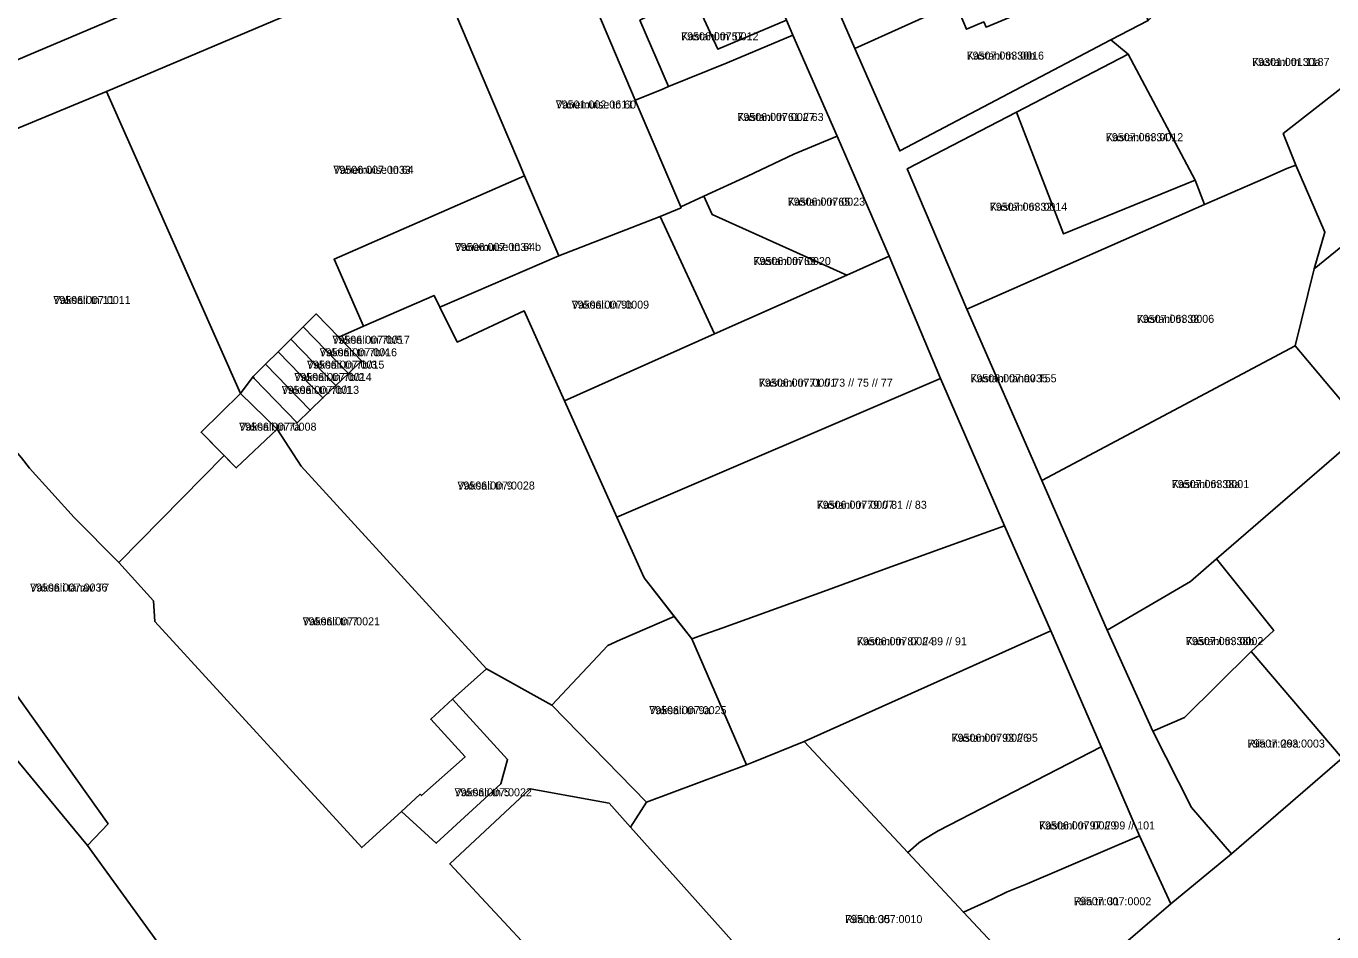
# Model space of a CAD drawing. Extents: x 643847 to 663718, y 6468443 to 6482775.
# Drawn here: x 658589.8 to 658834.6, y 6473255.6 to 6473425.5 of the extents above; entities that cross this region are included whole.
import ezdxf

# ---------------------------------------------------------------- set-up
doc = ezdxf.new("R2010")
doc.units = 0
for name, color, linetype in [('L_AADRESS', 7, 'Continuous'), ('PIIR', 7, 'Continuous'), ('TUNNUS', 7, 'Continuous')]:
    doc.layers.add(name, color=color, linetype=linetype)

msp = doc.modelspace()

# ---------------------------------------------------------------- linework, layer by layer
at = {"layer": 'PIIR'}
for points in [[(658352.42, 6473525.64), (658391.88, 6473482.08), (658396.74, 6473486.49), (658406.86, 6473476.1), (658413.24, 6473482), (658427.32, 6473466.48), (658432.48, 6473460.76), (658483.05, 6473404.88), (658577.8, 6473300.21), (658601.3, 6473271.83), (658617.93, 6473248.91), (658693.58, 6473165.93), (658667.09, 6473142.75), (658660.36, 6473146.34), (658618.09, 6473105.54), (658510.07, 6473222.36), (658505.7, 6473227.37), (658508.51, 6473230.27), (658490.61, 6473249.76), (658445.73, 6473274.17), (658391.3, 6473304.26), (658372.55, 6473316.25), (658325.22, 6473349.95)], [(658583.03, 6473417.07), (658626.66, 6473435.57), (658628.88, 6473436.51), (658649.93, 6473445.42), (658671, 6473454.4), (658691.92, 6473463.18), (658712.63, 6473472.01), (658724.84, 6473477.65), (658800.4, 6473509.39), (658804.98, 6473498.15), (658785.73, 6473489.74), (658737.94, 6473469.31), (658726.45, 6473464.29), (658718.34, 6473460.71), (658716.6, 6473461.47), (658716.02, 6473460.12), (658703.71, 6473454.91), (658702, 6473454.21), (658684.52, 6473446.9), (658665.58, 6473438.99), (658604.84, 6473413.21), (658567.57, 6473397.77)], [(658584.09, 6473493.04), (658592.12, 6473481.4), (658605.87, 6473488.59), (658612.19, 6473474.52), (658610.02, 6473473.51), (658626.66, 6473435.57), (658583.03, 6473417.07)], [(658738.91, 6473435.71), (658745.17, 6473421.3), (658753.55, 6473402.1), (658793.15, 6473422.92), (658796.36, 6473420.25), (658775.44, 6473409.35), (658754.98, 6473398.76), (658766.13, 6473372.39), (658780.18, 6473340.27), (658792.45, 6473312.19), (658800.98, 6473293.24), (658808.26, 6473278.98), (658815.73, 6473270.26), (658804.39, 6473260.9), (658798.53, 6473273.64), (658791.3, 6473290.35), (658781.9, 6473312.07), (658773.23, 6473331.78), (658761.22, 6473359.39), (658751.59, 6473382.33), (658741.84, 6473404.85), (658733.55, 6473423.79), (658732.32, 6473426.61)], [(658861.3, 6473404.41), (658831.27, 6473379.95), (658833.27, 6473386.84), (658827.82, 6473399.42), (658825.41, 6473405.35), (658846.27, 6473421.59)], [(658588.95, 6473344.51), (658590.42, 6473342.6), (658598.83, 6473333.37), (658607.16, 6473324.91), (658613.65, 6473317.73), (658613.9, 6473313.86), (658652.71, 6473271.43), (658660.14, 6473278.22), (658666.67, 6473272.25), (658678.8, 6473283.4), (658680.06, 6473287.95), (658669.74, 6473299.24), (658676.1, 6473304.96), (658688.34, 6473298.13), (658706.07, 6473279.98), (658703.1, 6473275.28), (658699.1, 6473279.76), (658684.26, 6473282.46), (658669.2, 6473268.37), (658718.1, 6473215.89)], [(658617.93, 6473248.91), (658601.3, 6473271.83), (658605.17, 6473275.88), (658568.09, 6473328.03)], [(658874.2, 6473286.88), (658829.76, 6473248.96), (658813.46, 6473235.12), (658760.72, 6473188.59), (658745.48, 6473177.42), (658741.68, 6473174.16), (658711.01, 6473147.88), (658693.58, 6473165.93), (658722.67, 6473191.45), (658735.36, 6473202.16), (658760.31, 6473223.21), (658781.85, 6473241.8), (658788.91, 6473247.59), (658804.39, 6473260.9), (658815.73, 6473270.26), (658836.52, 6473288.19)]]:
    msp.add_lwpolyline(points, dxfattribs=at)
for points in [[(658738.91, 6473435.71), (658761.36, 6473444.84), (658790.06, 6473456.51), (658797.34, 6473436.79), (658796.17, 6473436.34), (658769.74, 6473425.31), (658769.32, 6473426.29), (658766.08, 6473424.9), (658763.99, 6473429.83), (658745.17, 6473421.3)], [(658678.49, 6473408.6), (658665.58, 6473438.99), (658684.52, 6473446.9), (658688.6, 6473437.49), (658692.11, 6473429.63), (658695.69, 6473431.14), (658703.99, 6473411.63), (658712.5, 6473391.63), (658712.58, 6473391.44), (658708.65, 6473389.77), (658689.63, 6473382.39), (658683.25, 6473397.43), (658682.12, 6473400.09)], [(658732.32, 6473426.61), (658719.44, 6473421.18), (658714.73, 6473431.54), (658704.87, 6473426.6), (658710.23, 6473414.15), (658708.84, 6473413.58), (658703.99, 6473411.63), (658695.69, 6473431.14), (658709.42, 6473437.14), (658717.31, 6473440.56), (658724.8, 6473443.88)], [(658793.15, 6473422.92), (658800.14, 6473426.58), (658801.06, 6473427.49), (658829.43, 6473443.27), (658829.58, 6473443.61), (658829.98, 6473443.98), (658833.47, 6473439.91), (658832.15, 6473438.79), (658837.94, 6473432.06), (658839.37, 6473433.2), (658848.13, 6473422.91), (658846.57, 6473421.5), (658846.27, 6473421.59), (658825.41, 6473405.35), (658827.82, 6473399.42), (658826.14, 6473398.77), (658822.08, 6473396.98), (658810.71, 6473392.07), (658808.96, 6473396.59), (658796.36, 6473420.25)], [(658665.58, 6473438.99), (658678.49, 6473408.6), (658682.12, 6473400.09), (658683.25, 6473397.43), (658647.53, 6473381.78), (658653.02, 6473369.24), (658648.44, 6473367.16), (658644.19, 6473371.51), (658641.76, 6473369.09), (658639.44, 6473366.8), (658637.05, 6473364.44), (658634.7, 6473362.12), (658632.35, 6473359.79), (658630, 6473356.62), (658604.84, 6473413.21)], [(658753.55, 6473402.1), (658745.17, 6473421.3), (658763.99, 6473429.83), (658766.08, 6473424.9), (658769.32, 6473426.29), (658769.74, 6473425.31), (658796.17, 6473436.34), (658800.14, 6473426.58), (658793.15, 6473422.92)], [(658733.55, 6473423.79), (658721.2, 6473418.59), (658710.23, 6473414.15), (658704.87, 6473426.6), (658714.73, 6473431.54), (658719.44, 6473421.18), (658732.32, 6473426.61)], [(658741.84, 6473404.85), (658733.68, 6473401.49), (658725.03, 6473397.33), (658716.83, 6473393.61), (658712.5, 6473391.63), (658703.99, 6473411.63), (658708.84, 6473413.58), (658710.23, 6473414.15), (658721.2, 6473418.59), (658733.55, 6473423.79)], [(658775.44, 6473409.35), (658796.36, 6473420.25), (658808.96, 6473396.59), (658784.26, 6473386.53)], [(658496.72, 6473417.32), (658568.09, 6473328.03), (658605.17, 6473275.88), (658601.3, 6473271.83), (658577.8, 6473300.21), (658483.05, 6473404.88), (658493.36, 6473414.41)], [(658630, 6473356.62), (658622.6, 6473349.34), (658626.92, 6473344.94), (658607.16, 6473324.91), (658598.83, 6473333.37), (658590.42, 6473342.6), (658588.95, 6473344.51), (658575.52, 6473360.24), (658574.14, 6473361.52), (658559.79, 6473377.4), (658572.54, 6473382.28), (658572.66, 6473386.18), (658569.3, 6473394.9), (658567.57, 6473397.77), (658604.84, 6473413.21)], [(658754.98, 6473398.76), (658775.44, 6473409.35), (658784.26, 6473386.53), (658808.96, 6473396.59), (658810.71, 6473392.07), (658766.13, 6473372.39)], [(658751.59, 6473382.33), (658743.63, 6473378.79), (658718.4, 6473390.16), (658716.83, 6473393.61), (658725.03, 6473397.33), (658733.68, 6473401.49), (658741.84, 6473404.85)], [(658869.51, 6473315.83), (658840.95, 6473349.76), (658827.68, 6473365.53), (658831.27, 6473379.95), (658861.3, 6473404.41), (658909.1, 6473348.62)], [(658766.13, 6473372.39), (658810.71, 6473392.07), (658822.08, 6473396.98), (658826.14, 6473398.77), (658827.82, 6473399.42), (658833.27, 6473386.84), (658831.27, 6473379.95), (658827.68, 6473365.53), (658780.18, 6473340.27)], [(658683.25, 6473397.43), (658689.63, 6473382.39), (658667.36, 6473372.77), (658666.26, 6473374.99), (658653.02, 6473369.24), (658647.53, 6473381.78)], [(658718.85, 6473367.76), (658708.65, 6473389.77), (658712.58, 6473391.44), (658712.5, 6473391.63), (658716.83, 6473393.61), (658718.4, 6473390.16), (658743.63, 6473378.79)], [(658718.85, 6473367.76), (658690.72, 6473355.25), (658683.14, 6473372.11), (658670.62, 6473366.24), (658667.36, 6473372.77), (658689.63, 6473382.39), (658708.65, 6473389.77)], [(658761.22, 6473359.39), (658700.53, 6473333.43), (658690.72, 6473355.25), (658718.85, 6473367.76), (658743.63, 6473378.79), (658751.59, 6473382.33)], [(658688.34, 6473298.13), (658676.1, 6473304.96), (658641.38, 6473342.97), (658636.85, 6473349.89), (658630, 6473356.62), (658632.35, 6473359.79), (658632.53, 6473359.42), (658640.59, 6473351.07), (658643.07, 6473353.46), (658645.44, 6473355.76), (658647.86, 6473358.09), (658650.2, 6473360.36), (658652.67, 6473362.75), (658648.44, 6473367.16), (658653.02, 6473369.24), (658666.26, 6473374.99), (658667.36, 6473372.77), (658670.62, 6473366.24), (658683.14, 6473372.11), (658690.72, 6473355.25), (658700.53, 6473333.43), (658705.65, 6473322.03), (658711.3, 6473314.8), (658701.16, 6473310.38), (658698.87, 6473309.34)], [(658641.76, 6473369.09), (658644.19, 6473371.51), (658648.44, 6473367.16), (658652.67, 6473362.75), (658650.2, 6473360.36)], [(658639.44, 6473366.8), (658641.76, 6473369.09), (658650.2, 6473360.36), (658647.86, 6473358.09)], [(658637.05, 6473364.44), (658639.44, 6473366.8), (658647.86, 6473358.09), (658645.44, 6473355.76)], [(658780.18, 6473340.27), (658827.68, 6473365.53), (658840.95, 6473349.76), (658812.96, 6473325.59), (658808.04, 6473321.35), (658792.45, 6473312.19)], [(658634.7, 6473362.12), (658637.05, 6473364.44), (658645.44, 6473355.76), (658643.07, 6473353.46)], [(658632.53, 6473359.42), (658632.35, 6473359.79), (658634.7, 6473362.12), (658643.07, 6473353.46), (658640.59, 6473351.07)], [(658773.23, 6473331.78), (658750.52, 6473323.56), (658739.27, 6473319.49), (658720.42, 6473312.67), (658716.81, 6473311.37), (658714.6, 6473310.57), (658705.65, 6473322.03), (658700.53, 6473333.43), (658761.22, 6473359.39)], [(658622.6, 6473349.34), (658630, 6473356.62), (658636.85, 6473349.89), (658629.18, 6473342.63)], [(658613.9, 6473313.86), (658613.65, 6473317.73), (658607.16, 6473324.91), (658626.92, 6473344.94), (658629.18, 6473342.63), (658636.85, 6473349.89), (658641.38, 6473342.97), (658676.1, 6473304.96), (658669.74, 6473299.24), (658665.64, 6473295.49), (658672.07, 6473288.47), (658663.9, 6473281.18), (658663.66, 6473281.45), (658660.14, 6473278.22), (658652.71, 6473271.43)], [(658836.52, 6473288.19), (658819.41, 6473308.19), (658823.67, 6473312.18), (658812.96, 6473325.59), (658840.95, 6473349.76), (658869.51, 6473315.83)], [(658773.23, 6473331.78), (658781.9, 6473312.07), (658735.62, 6473291.33), (658726.08, 6473287.44), (658724.83, 6473286.98), (658714.6, 6473310.57), (658716.81, 6473311.37), (658720.42, 6473312.67), (658739.27, 6473319.49), (658750.52, 6473323.56)], [(658792.45, 6473312.19), (658808.04, 6473321.35), (658812.96, 6473325.59), (658823.67, 6473312.18), (658819.41, 6473308.19), (658806.95, 6473295.85), (658800.98, 6473293.24)], [(658688.34, 6473298.13), (658698.87, 6473309.34), (658701.16, 6473310.38), (658711.3, 6473314.8), (658714.6, 6473310.57), (658724.83, 6473286.98), (658706.07, 6473279.98)], [(658781.9, 6473312.07), (658791.3, 6473290.35), (658760.79, 6473274.56), (658757.74, 6473272.75), (658757.12, 6473272.3), (658755.07, 6473270.49), (658735.62, 6473291.33)], [(658815.73, 6473270.26), (658808.26, 6473278.98), (658800.98, 6473293.24), (658806.95, 6473295.85), (658819.41, 6473308.19), (658836.52, 6473288.19)], [(658660.14, 6473278.22), (658663.66, 6473281.45), (658663.9, 6473281.18), (658672.07, 6473288.47), (658665.64, 6473295.49), (658669.74, 6473299.24), (658680.06, 6473287.95), (658678.8, 6473283.4), (658666.67, 6473272.25)], [(658735.62, 6473291.33), (658755.07, 6473270.49), (658765.5, 6473259.32), (658776.42, 6473247.62), (658781.85, 6473241.8), (658760.31, 6473223.21), (658740.7, 6473245.26), (658734.73, 6473239.88), (658703.1, 6473275.28), (658706.07, 6473279.98), (658724.83, 6473286.98), (658726.08, 6473287.44)], [(658791.3, 6473290.35), (658798.53, 6473273.64), (658777.43, 6473264.66), (658773.69, 6473263.13), (658770.89, 6473261.76), (658765.5, 6473259.32), (658755.07, 6473270.49), (658757.12, 6473272.3), (658757.74, 6473272.75), (658760.79, 6473274.56)], [(658669.2, 6473268.37), (658684.26, 6473282.46), (658699.1, 6473279.76), (658703.1, 6473275.28), (658734.73, 6473239.88), (658739.22, 6473234.86), (658718.1, 6473215.89)], [(658804.39, 6473260.9), (658788.91, 6473247.59), (658783.63, 6473253.54), (658776.42, 6473247.62), (658765.5, 6473259.32), (658770.89, 6473261.76), (658773.69, 6473263.13), (658777.43, 6473264.66), (658798.53, 6473273.64)]]:
    msp.add_lwpolyline(points, close=True, dxfattribs=at)

# ---------------------------------------------------------------- texts
at = {"layer": 'L_AADRESS'}
for s, p in [('Kastani tn 57', (658712.58, 6473422.84)), ('Kastani tn 30b', (658766.1, 6473419.22)), ('Kastani tn 30a', (658819.62, 6473418.03)), ('Vanemuise tn 60', (658689.08, 6473410.05)), ('Kastani tn 61 // 63', (658723.12, 6473407.71)), ('Kastani tn 34', (658792.2, 6473403.92)), ('Vanemuise tn 64', (658647.39, 6473397.8)), ('Kastani tn 65', (658732.56, 6473391.82)), ('Kastani tn 32', (658770.45, 6473390.87)), ('Vanemuise tn 64b', (658670.15, 6473383.33)), ('Kastani tn 69', (658726.14, 6473380.69)), ('Vaksali tn 11', (658594.89, 6473373.39)), ('Vaksali tn 9b', (658692.07, 6473372.51)), ('Kastani tn 38', (658798, 6473369.85)), ('Vaksali tn 7b/5', (658647.21, 6473365.93)), ('Vaksali tn 7b/4', (658644.82, 6473363.58)), ('Vaksali tn 7b/3', (658642.45, 6473361.26)), ('Vaksali tn 7b/2', (658640.07, 6473358.94)), ('Kastani tänav T55', (658766.8, 6473358.7)), ('Vaksali tn 7b/1', (658637.71, 6473356.53)), ('Kastani tn 71 // 73 // 75 // 77', (658727.16, 6473357.88)), ('Vaksali tn 7a', (658629.73, 6473349.62)), ('Vaksali tn 9', (658670.65, 6473338.59)), ('Kastani tn 38a', (658804.56, 6473338.86)), ('Kastani tn 79 // 81 // 83', (658738, 6473334.98)), ('Vaksali tänav T7', (658590.54, 6473319.46)), ('Vaksali tn 7', (658641.63, 6473313.12)), ('Kastani tn 87 // 89 // 91', (658745.51, 6473309.38)), ('Kastani tn 38b', (658807.21, 6473309.41)), ('Vaksali tn 9a', (658706.59, 6473296.46)), ('Kastani tn 93 // 95', (658763.28, 6473291.28)), ('Riia tn 29a', (658818.75, 6473290.2)), ('Vaksali tn 5', (658670.1, 6473281.06)), ('Kastani tn 97 // 99 // 101', (658779.67, 6473274.84)), ('Riia tn 31', (658786.21, 6473260.62)), ('Riia tn 35', (658743.3, 6473257.27))]:
    msp.add_text(s, height=1.5, dxfattribs=at).set_placement(p)
at = {"layer": 'TUNNUS'}
for s, p in [('79506:007:0012', (658712.58, 6473422.84)), ('79507:063:0016', (658766.1, 6473419.22)), ('79301:001:1187', (658819.62, 6473418.03)), ('79501:002:0611', (658689.08, 6473410.05)), ('79506:007:0027', (658723.12, 6473407.71)), ('79507:063:0012', (658792.2, 6473403.92)), ('79506:007:0033', (658647.39, 6473397.8)), ('79506:007:0023', (658732.56, 6473391.82)), ('79507:063:0014', (658770.45, 6473390.87)), ('79506:007:0034', (658670.15, 6473383.33)), ('79506:007:0020', (658726.14, 6473380.69)), ('79506:007:0011', (658594.89, 6473373.39)), ('79506:007:0009', (658692.07, 6473372.51)), ('79507:063:0006', (658798, 6473369.85)), ('79506:007:0017', (658647.21, 6473365.93)), ('79506:007:0016', (658644.82, 6473363.58)), ('79506:007:0015', (658642.45, 6473361.26)), ('79506:007:0014', (658640.07, 6473358.94)), ('79506:007:0035', (658766.8, 6473358.7)), ('79506:007:0013', (658637.71, 6473356.53)), ('79506:007:0001', (658727.16, 6473357.88)), ('79506:007:0008', (658629.73, 6473349.62)), ('79506:007:0028', (658670.65, 6473338.59)), ('79507:063:0001', (658804.56, 6473338.86)), ('79506:007:0007', (658738, 6473334.98)), ('79506:007:0036', (658590.54, 6473319.46)), ('79506:007:0021', (658641.63, 6473313.12)), ('79506:007:0024', (658745.51, 6473309.38)), ('79507:063:0002', (658807.21, 6473309.41)), ('79506:007:0025', (658706.59, 6473296.46)), ('79506:007:0026', (658763.28, 6473291.28)), ('79507:063:0003', (658818.75, 6473290.2)), ('79506:007:0022', (658670.1, 6473281.06)), ('79506:007:0029', (658779.67, 6473274.84)), ('79507:007:0002', (658786.21, 6473260.62)), ('79506:007:0010', (658743.3, 6473257.27))]:
    msp.add_text(s, height=1.5, dxfattribs=at).set_placement(p)

doc.saveas('drawing.dxf')
